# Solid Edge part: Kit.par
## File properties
Author: bmolnar
Last saved by: bmolnar
Revision: 76
Sűrűség: 0,000 kg/m^3
Pontosság: 0,990
Username: bmolnar
Dokumentum tartalom típus: 0
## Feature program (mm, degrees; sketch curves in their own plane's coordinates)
base feature "unnamed BaseFeature 1"
sketch for "Furat_1" plane through (-18.15, -81.65, 0) normal (1, 0, 0) x-axis (0, 0, 1)
  hole centre (0, -13.85) bore radius 2.067
hole "Furat_1" nominal diameter 5 finite  ThreadDepth = 5 mm; StartChamferOffset = 0.6 mm; StartChamferAngle = 45 deg
sketch for "Furat_2" plane through (-11, -70.2, -11) normal (0, -1, 0) x-axis (0, 0, 1)
  hole centre (0, 0) bore radius 2.067
hole "Furat_2" nominal diameter 5
sketch for "unnamed Hole 1" plane through (-11, -70.2, -11) normal (0, -1, 0) x-axis (0, 0, 1)
  hole centre (22, 0) bore radius 2.067
hole "unnamed Hole 1"
sketch for "unnamed Hole 2" plane through (-11, -70.2, -11) normal (0, -1, 0) x-axis (0, 0, 1)
  hole centre (22, -22) bore radius 2.067
hole "unnamed Hole 2"
sketch for "unnamed Hole 3" plane through (-11, -70.2, -11) normal (0, -1, 0) x-axis (0, 0, 1)
  hole centre (0, -22) bore radius 2.067
hole "unnamed Hole 3"
pattern "unnamed Pattern 1" of "Furat_2", "unnamed Hole 1", "unnamed Hole 2", "unnamed Hole 3"
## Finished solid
Body 1: solid body, 258 faces, 616 edges, 372 vertices, 2 internal voids.
  Faces by surface: plane 124, cylinder 58, swept 43, cone 26, torus 7
  Edges by curve: line 361, circle 155, spline 90, curve on surface 5, intersection 4, ellipse 1
Bounding box of the edges (mm; curved faces can reach further): 36.300 x 11.800 x 36.300, from (-18.15, -75.3, -18.15) to (18.15, -63.5, 18.15).
Cylindrical faces by radius (mm): R0.2 x18, R0.4307 x1, R0.4865 x1, R2.067 x5, R3.75 x2, R4 x4, R4.1 x12, R5.24 x1, R5.45 x2, R5.55 x2, R5.7 x1, R6 x1, R6.92 x1, R7 x1, R11.25 x6
Conical faces (half-angle, radius in mm at the cone's reference point): 0.5 deg R4.5 x4, 3 deg R6.96 x1, 7 deg R6.4156 x1, 14 deg R5.12 x1, 14 deg R5.3801 x1, 17 deg R5.12 x1, 23 deg R5.7369 x1, 42.5 deg R5.1096 x1, 45 deg R2.317 x2, 45 deg R2.367 x2, 45 deg R2.667 x1, 45 deg R4.25 x2, 45 deg R5.3 x2, 45 deg R5.35 x2, 45 deg R5.85 x1, 84 deg R5.4096 x1, 85 deg R6.73 x1, 87 deg R5.1371 x1
Toroidal faces (ring radius, tube radius in mm): R3.8 r0.2 x2, R4.4 r0.4 x2, R5.6606 r0.18 x1, R6.1131 r0.26 x1, R6.72 r0.2 x1
Planar faces by outward normal: +x 5, +y 4, +z 15, -x 7, -y 16, -z 13, oblique 64
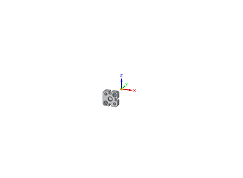
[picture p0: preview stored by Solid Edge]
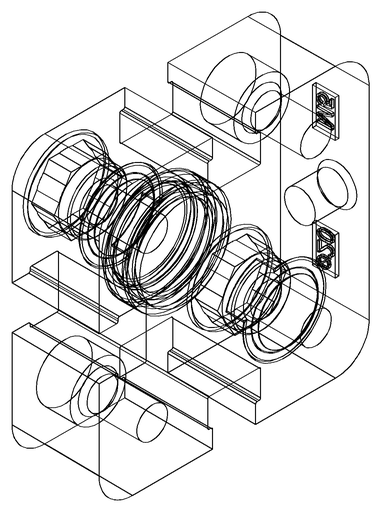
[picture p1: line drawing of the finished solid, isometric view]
